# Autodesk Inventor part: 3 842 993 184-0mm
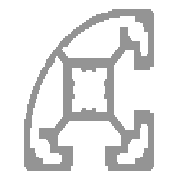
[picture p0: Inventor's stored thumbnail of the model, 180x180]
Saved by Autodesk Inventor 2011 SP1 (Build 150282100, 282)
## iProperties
Category: End -/-
Created: 2011-02
Part Number: 3 842 993 184-0mm
Document SubType Name: Modeling
Designer: SRW
Density: 2.71 g/cm^3
Categories: <MemberInstance><Categories><Category DisplayName="Structural Shapes" InternalName="089c4875-fa83-4c05-b084-43b9cc11f5ed" Mnemonic="GRDR"><CategoryParameter Dis
Stock Number: 3 842 993 184
Description: PROFILE 40x40R, -/-
Material: Aluminum-6061
Mass: 33.1572 g
Surface Area: 125.391 cm^2
Volume: 12.2351 cm^3
G_L: 25.000 mm
Author: SRW
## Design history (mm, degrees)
node "Blocks"
  sketch "40X40R"
    geometry: L1 (50.697, 39.13)-(50.697, 40.381); L2 (54.697, 36.38)-(53.447, 36.38); L3 (54.697, 31.38)-(54.697, 36.38); L4 (42.783, 29.88)-(45.635, 32.733); L5 (45.635, 32.733)-(45.635, 36.38); L6 (51.697, 33.169)-(51.697, 31.38); L7 (46.635, 37.38)-(47.486, 37.38); L8 (50.697, 40.381)-(49.481, 40.38); L9 (56.197, 4.511)-(56.197, 16.08); L10 (56.197, 16.08)-(54.697, 16.08); L11 (53.447, 7.38)-(54.697, 7.38); L12 (54.697, 16.08)-(54.697, 16.88); L13 (54.697, 7.38)-(54.697, 12.38); L14 (51.697, 12.38)-(51.697, 10.13); L15 (51.697, 10.13)-(50.697, 10.13); L16 (50.697, 3.38)-(50.697, 4.63); L17 (54.697, 16.88)-(50.197, 16.88); L18 (50.197, 16.88)-(50.197, 11.83); L19 (47.947, 7.38)-(47.947, 6.38); L20 (46.247, 10.416)-(46.247, 7.88); L21 (47.947, 6.38)-(45.697, 6.38); L22 (45.697, 3.38)-(50.697, 3.38); L23 (41.997, 1.88)-(53.566, 1.88); L24 (41.997, 3.38)-(41.997, 1.88); L25 (41.197, 3.38)-(41.997, 3.38); L26 (41.197, 7.88)-(41.197, 3.38); L27 (50.197, 11.83)-(47.661, 11.83); L28 (38.195, 17.297)-(38.595, 16.38); L29 (38.595, 27.38)-(38.195, 26.464); L30 (38.595, 16.38)-(41.697, 16.38); L31 (41.697, 27.38)-(38.595, 27.38); L32 (41.697, 16.38)-(41.697, 19.482); L33 (41.697, 19.482)-(40.781, 19.882); L34 (40.781, 23.879)-(41.697, 24.278); L35 (41.697, 24.278)-(41.697, 27.38); L36 (43.697, 15.795)-(43.697, 27.966); L37 (46.247, 7.88)-(41.197, 7.88); L38 (42.283, 14.38)-(46.247, 10.416); L39 (47.661, 11.83)-(43.697, 15.795); L40 (43.697, 27.966)-(47.661, 31.93); L41 (50.197, 31.93)-(50.197, 26.88); L42 (26.147, 10.416)-(30.111, 14.38); L43 (26.147, 7.88)-(26.147, 10.416); L44 (31.197, 7.88)-(26.147, 7.88); L45 (31.197, 3.38)-(31.197, 7.88); L46 (30.397, 3.38)-(31.197, 3.38); L47 (30.397, 1.88)-(30.397, 3.38); L48 (18.828, 1.88)-(30.397, 1.88); L49 (16.197, 8.58)-(16.197, 4.511); L50 (17.697, 8.597)-(17.697, 7.38); L51 (17.697, 7.38)-(18.947, 7.38); L52 (25.345, 12.442)-(28.197, 15.295); L53 (21.697, 12.442)-(25.345, 12.442); L54 (20.697, 10.592)-(20.697, 11.442); L55 (21.697, 3.38)-(26.697, 3.38); L56 (21.697, 4.63)-(21.697, 3.38); L57 (26.697, 6.38)-(24.909, 6.38); L58 (33.799, 16.38)-(34.199, 17.297); L59 (34.199, 26.464)-(33.799, 27.38); L60 (30.111, 14.38)-(42.283, 14.38); L61 (29.611, 29.88)-(42.783, 29.88); L62 (30.697, 16.38)-(33.799, 16.38); L63 (33.799, 27.38)-(30.697, 27.38); L64 (31.614, 19.882)-(30.697, 19.482)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; A1 r 2.75 centre (50.697, 36.38) between (53.447, 36.38) and (50.697, 39.13); A2 r 31.8 centre (49.497, 8.58) between (49.481, 40.38) and (27.729, 31.762); A3 r 1.5 centre (53.197, 31.38) between (51.697, 31.38) and (54.697, 31.38); A4 r 0.5 centre (51.197, 33.169) between (51.697, 33.169) and (51.12, 33.663); A5 r 0.5 centre (47.486, 36.88) between (47.98, 36.803) and (47.486, 37.38); A6 r 2.75 centre (50.697, 36.38) between (47.98, 36.803) and (51.12, 33.663); A7 r 1 centre (46.635, 36.38) between (46.635, 37.38) and (45.635, 36.38); A8 r 2.631 centre (53.566, 4.511) between (53.566, 1.88) and (56.197, 4.511); A9 r 1.5 centre (53.197, 12.38) between (54.697, 12.38) and (51.697, 12.38); A10 r 2.75 centre (50.697, 7.38) between (50.697, 4.63) and (53.447, 7.38); A11 r 2.75 centre (50.697, 7.38) between (50.697, 10.13) and (47.947, 7.38); A12 r 1.5 centre (45.697, 4.88) between (45.697, 6.38) and (45.697, 3.38); A13 r 5 centre (36.197, 21.88) between (40.781, 19.882) and (40.781, 23.879); A14 r 2.631 centre (18.828, 4.511) between (16.197, 4.511) and (18.828, 1.88); A15 r 2.75 centre (21.697, 7.38) between (18.947, 7.38) and (21.697, 4.63); A16 r 1 centre (21.697, 11.442) between (21.697, 12.442) and (20.697, 11.442); A17 r 0.5 centre (21.197, 10.592) between (20.697, 10.592) and (21.274, 10.098); A18 r 0.5 centre (24.909, 6.88) between (24.414, 6.957) and (24.909, 6.38); A19 r 2.75 centre (21.697, 7.38) between (24.414, 6.957) and (21.274, 10.098); A20 r 1.5 centre (26.697, 4.88) between (26.697, 3.38) and (26.697, 6.38); A21 r 5 centre (36.197, 21.88) between (34.199, 17.297) and (38.195, 17.297); A22 r 5 centre (36.197, 21.88) between (38.195, 26.464) and (34.199, 26.464); A23 r 33.3 centre (49.497, 8.58) between (49.497, 41.88) and (16.197, 8.58); A24 r 5 centre (36.197, 21.88) between (31.614, 23.879) and (31.614, 19.882); A25 r 31.8 centre (49.497, 8.58) between (26.315, 30.348) and (17.697, 8.597); A26 r 2.631 centre (53.566, 39.25) between (56.197, 39.25) and (53.566, 41.88); 1 further point
    constraints: 152 end point, 52 point on circle, 26 centre point, 1 coincident
node "Start Plane"
node "End Plane"
sketch "Sketch48"
  geometry: 1 further point
  constraints: 1 other
extrude "Extrusion14" join sketch "Sketch48" stored distance "d96" = 10; taper "d97" = 0 deg
node "Driven Length"
  sketch "Sketch55"
    geometry: L1 (0, 0)-(10, 0) reference
    constraints: 2 end point, 1 horizontal
  workplane "Work Plane23"
  sketch "Sketch56"
    geometry: L1 (-28, 0)-(28, 0) reference; L2 (-28, 25)-(28, 25) reference
    dimensions: "d7" = 25 distance between parallel lines of L1 L2 (derived)
sketch "Sketch9"
  geometry: 1 further point
hole "M12/-" sketch "Sketch9" at (0, 0) diameter "d17" = 10.106; stored, may be unused: countersink angle "d21" = 90 deg, drill point angle "d23" = 118 deg; dims "d18" = 6, "d19" = 4, "d20" = 2, "d22" = 55
sketch "Sketch10"
  geometry: 1 further point
hole "-/M12" sketch "Sketch10" at (0, 0) diameter "d24" = 10.106; stored, may be unused: countersink angle "d28" = 90 deg, drill point angle "d30" = 118 deg; dims "d25" = 6, "d26" = 4, "d27" = 2, "d29" = 55
sketch "Sketch11"
  geometry: L1 (-13.7, 0)-(12.2, 0) reference; C1 r 8.5 at (0, 20); 1 further point
  constraints: 1 centre point, 1 vertical alignment
  dimensions: "d31" = 20 distance from line of C1.centre L1; "d32" = 17 diameter of C1
extrude "D17/-" cut sketch "Sketch11" stored distance "d33" = 10; taper "d34" = 0 deg
sketch "Sketch12"
  geometry: L1 (-13.7, 25)-(12.2, 25) reference; C1 r 8.5 at (0, 5); 1 further point
  constraints: 1 centre point, 1 vertical alignment
  dimensions: "d35" = 17 diameter of C1; "d36" = 20 distance from line of L1 C1.centre
extrude "-/D17" cut sketch "Sketch12" stored distance "d37" = 10; taper "d38" = 0 deg
sketch "Sketch13"
  geometry: L1 (-12.98, 0)-(7.88, 0) reference; C1 r 4.9 at (0, 20); 1 further point
  constraints: 1 centre point, 1 vertical alignment
  dimensions: "d39" = 9.8 diameter of C1; "d40" = 20 distance from line of C1.centre L1
extrude "D9.8/-" cut sketch "Sketch13" stored distance "d41" = 10; taper "d42" = 0 deg
sketch "Sketch14"
  geometry: L1 (-12.98, 25)-(7.88, 25) reference; C1 r 4.9 at (0, 5); 1 further point
  constraints: 1 centre point, 1 vertical alignment
  dimensions: "d43" = 9.8 diameter of C1; "d44" = 20 distance from line of L1 C1.centre
extrude "-/D9.8" cut sketch "Sketch14" stored distance "d45" = 10; taper "d46" = 0 deg
sketch "Sketch15"
  geometry: L1 (-6.86, 25)-(6.86, 25) reference; C1 r 4.9 at (0, 5); 1 further point
  constraints: 1 centre point, 1 vertical alignment
  dimensions: "d47" = 9.8 diameter of C1; "d48" = 20 distance from line of L1 C1.centre
extrude "-/D9.8VS" cut sketch "Sketch15" stored distance "d49" = 10; taper "d50" = 0 deg
sketch "Sketch26"
  geometry: L1 (-6.86, 0)-(6.86, 0) reference; C1 r 4.9 at (0, 20); 1 further point
  constraints: 1 centre point, 1 vertical alignment
  dimensions: "d62" = 9.8 diameter of C1; "d65" = 20 distance from line of L1 C1.centre
extrude "D9.8VS/-" cut sketch "Sketch26" stored distance "d63" = 10; taper "d64" = 0 deg
sketch "Sketch37"
  geometry: L1 (-11.9, 0)-(11.9, 0) reference; L2 (-11.9, 25)-(11.9, 25) reference; C1 r 8.5 at (0, 20); 1 further point
  constraints: 1 centre point, 1 vertical alignment
  dimensions: "d76" = 20 distance from line of C1.centre L1; "d77" = 17 diameter of C1
extrude "D17VS/-" cut sketch "Sketch37" stored distance "d78" = 10; taper "d79" = 0 deg
sketch "Sketch38"
  geometry: L1 (-11.9, 25)-(11.9, 25) reference; C1 r 8.5 at (0, 5); 1 further point
  constraints: 1 centre point, 1 vertical alignment
  dimensions: "d80" = 17 diameter of C1; "d81" = 20 distance from line of L1 C1.centre
extrude "-/D17VS" cut sketch "Sketch38" stored distance "d82" = 10; taper "d83" = 0 deg
body "Solid1"
node "40X40R:1"
other parameters: "Length" = 25, "G_OFFSET_START" = 0 [user parameter; used in 2 equation terms], "G_OFFSET_END" = 0 [user parameter; used in 2 equation terms], "d2" = 0 (computed from G_OFFSET_START), "d3" = 25 (= Length + G_OFFSET_END), "G_L" = 25 (= d7) [user parameter], "Length2" = 25 (= G_OFFSET_START + Length + G_OFFSET_END) [user parameter], "d104" = 90 deg
